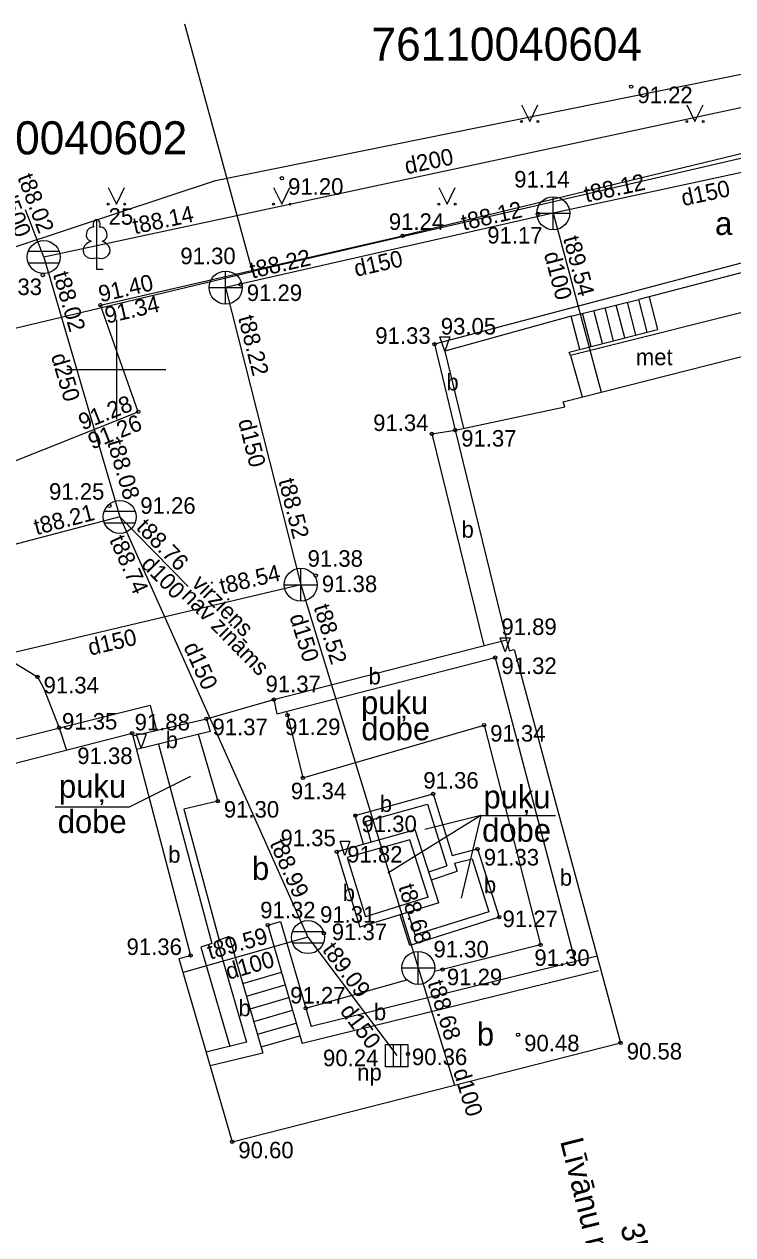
# Model space of a CAD drawing. Extents: x 634272 to 634544, y 247463 to 247653.
# Drawn here: x 634397.21 to 634418.64, y 247573.83 to 247610.44 of the extents above; entities that cross this region are included whole.
import ezdxf

# ---------------------------------------------------------------- set-up
doc = ezdxf.new("R2010")
doc.units = 0
for name, color, linetype in [('BUVE_BDET_####_####_#', 7, 'Continuous'), ('BUVE_BDET_####_TKST_#', 7, 'Continuous'), ('BUVE_EKAS_####_####_#', 7, 'Continuous'), ('BUVE_EKAS_BIZM_TKST_#', 7, 'Continuous'), ('BUVE_EKAS_RAKS_TKST_#', 7, 'Continuous'), ('CELI_CAPM_####_####_#', 7, 'Continuous'), ('CELI_CMAL_####_####_#', 7, 'Continuous'), ('CELI_CSEG_####_TKST_#', 7, 'Continuous'), ('GEOD_ELEM_####_####_#', 7, 'Continuous'), ('LKAN_ELEM_####_####_#', 7, 'Continuous'), ('LKAN_ELEM_PAST_TKST_#', 7, 'Continuous'), ('LKAN_VADP_PAST_####_#', 7, 'Continuous'), ('LKAN_VADP_PAST_TKST_#', 7, 'Continuous'), ('RAMI_UZMR_####_####_#', 7, 'Continuous'), ('RELJ_AATZ_####_TKST_#', 7, 'Continuous'), ('RELJ_ELEM_####_####_#', 7, 'Continuous'), ('ROBZ_KADS_####_TKST_#', 7, 'Continuous'), ('ROBZ_UZMR_####_####_#', 7, 'Continuous'), ('SKAN_ELEM_####_####_#', 7, 'Continuous'), ('SKAN_ELEM_PAST_TKST_#', 7, 'Continuous'), ('SKAN_VADP_PAST_####_#', 7, 'Continuous'), ('SKAN_VADP_PAST_TKST_#', 7, 'Continuous'), ('TERT_DIAM_####_TKST_#', 7, 'Continuous'), ('TERT_ELEM_####_####_#', 7, 'Continuous'), ('TERT_IZMT_####_TKST_#', 7, 'Continuous')]:
    doc.layers.add(name, color=color, linetype=linetype)

msp = doc.modelspace()

# ---------------------------------------------------------------- linework, layer by layer
at = {"layer": 'BUVE_BDET_####_####_#'}
for p, q in [((634415.714, 247601.044), (634415.459, 247602.033)), ((634416.053, 247601.131), (634415.798, 247602.116)), ((634416.372, 247601.214), (634416.12, 247602.189)), ((634414.02, 247600.605), (634413.759, 247601.615)), ((634414.359, 247600.693), (634414.099, 247601.699)), ((634414.698, 247600.781), (634414.439, 247601.782)), ((634415.037, 247600.868), (634414.779, 247601.866)), ((634415.376, 247600.956), (634415.119, 247601.949)), ((634407.47, 247585.638), (634407.227, 247586.507)), ((634407.711, 247585.705), (634407.535, 247586.333)), ((634409.449, 247584.803), (634409.992, 247584.985)), ((634409.435, 247584.035), (634407.533, 247583.447)), ((634409.751, 247583.871), (634407.368, 247583.134)), ((634404.965, 247583.308), (634405.888, 247580.131)), ((634404.577, 247583.195), (634405.617, 247579.617)), ((634403.046, 247582.719), (634403.937, 247579.652)), ((634403.407, 247582.855), (634404.432, 247579.326)), ((634414.542, 247582.253), (634405.888, 247580.131)), ((634403.821, 247581.429), (634404.991, 247581.769)), ((634403.933, 247581.045), (634405.103, 247581.385)), ((634404.045, 247580.661), (634405.215, 247581.001)), ((634404.156, 247580.277), (634405.326, 247580.617)), ((634404.268, 247579.893), (634405.438, 247580.233)), ((634403.937, 247579.652), (634402.714, 247579.352)), ((634404.379, 247579.509), (634405.549, 247579.849))]:
    msp.add_line(p, q, dxfattribs=at)
for points in [[(634424.638, 247604.603), (634424.692, 247604.432), (634415.797, 247602.116)], [(634421.031, 247603.777), (634409.625, 247600.763)], [(634421.911, 247601.206), (634420.687, 247600.92), (634422.13, 247595.421), (634421.912, 247595.323), (634420.138, 247602.03), (634413.732, 247600.418), (634413.69, 247600.52), (634416.369, 247601.213)], [(634413.759, 247601.615), (634415.797, 247602.116)], [(634413.759, 247601.615), (634409.931, 247600.553), (634410.496, 247598.221)], [(634409.625, 247600.763), (634410.243, 247598.168)], [(634413.732, 247600.418), (634414.092, 247599.169)], [(634409.541, 247598.049), (634410.243, 247598.168)], [(634409.541, 247598.049), (634411.109, 247591.647)], [(634404.764, 247590.016), (634411.797, 247591.824)], [(634404.848, 247589.588), (634411.46, 247591.288)], [(634411.46, 247591.288), (634413.872, 247582.088)], [(634404.764, 247590.016), (634404.848, 247589.588)], [(634401.024, 247589.834), (634389.457, 247586.939), (634390.714, 247581.751), (634391.293, 247581.906), (634391.704, 247580.059), (634391.004, 247579.905), (634391.958, 247576.222)], [(634401.024, 247589.834), (634401.217, 247589.086)], [(634400.501, 247588.918), (634402.721, 247589.438), (634402.832, 247589.051), (634400.608, 247588.51)], [(634401.274, 247588.672), (634402.884, 247582.635), (634402.556, 247582.531), (634403.431, 247579.528)], [(634407.227, 247586.507), (634409.579, 247587.163), (634410.155, 247585.305)], [(634407.535, 247586.333), (634409.412, 247586.857), (634409.992, 247584.985)], [(634409.751, 247583.871), (634409.036, 247586.076), (634406.663, 247585.412)], [(634409.435, 247584.035), (634408.872, 247585.771), (634406.978, 247585.24), (634407.533, 247583.447)], [(634410.155, 247585.305), (634410.926, 247585.497), (634411.579, 247583.435), (634408.875, 247582.582), (634408.582, 247583.51)], [(634406.663, 247585.412), (634407.368, 247583.134)], [(634410.229, 247585.065), (634410.759, 247585.198), (634411.265, 247583.598), (634409.038, 247582.896), (634408.821, 247583.584)], [(634409.526, 247584.565), (634410.303, 247584.825)], [(634410.229, 247585.065), (634410.303, 247584.825)], [(634404.577, 247583.195), (634404.965, 247583.308)], [(634403.407, 247582.855), (634403.046, 247582.719)], [(634414.582, 247581.815), (634405.617, 247579.617)], [(634404.432, 247579.326), (634402.836, 247578.935)]]:
    msp.add_lwpolyline(points, dxfattribs=at)
at = {"layer": 'BUVE_EKAS_####_####_#'}
for p, q in [((634411.88, 247591.488), (634412.036, 247591.53)), ((634401.891, 247582.186), (634402.242, 247582.278)), ((634401.891, 247582.186), (634403.502, 247576.642))]:
    msp.add_line(p, q, dxfattribs=at)
for points in [[(634410.243, 247598.168), (634413.566, 247598.866), (634413.511, 247599.021), (634419.188, 247600.462)], [(634410.243, 247598.168), (634411.88, 247591.488)], [(634412.036, 247591.53), (634415.25, 247579.63)], [(634390.22, 247586.366), (634400.481, 247588.996)], [(634400.481, 247588.996), (634402.242, 247582.278)], [(634403.502, 247576.642), (634415.25, 247579.63)]]:
    msp.add_lwpolyline(points, dxfattribs=at)
at = {"layer": 'CELI_CAPM_####_####_#'}
for points in [[(634426.327, 247605.556), (634425.634, 247608.152), (634408.658, 247604.045)], [(634380.207, 247592.753), (634383.979, 247594.191), (634384.583, 247592.406), (634392.046, 247595.29), (634400.663, 247598.72), (634399.516, 247601.947), (634408.658, 247604.045)], [(634395.598, 247591.923), (634397.613, 247590.703), (634397.795, 247590.369), (634398.265, 247589.164), (634398.489, 247588.485)]]:
    msp.add_lwpolyline(points, dxfattribs=at)
at = {"layer": 'CELI_CMAL_####_####_#'}
for points in [[(634402.721, 247589.438), (634404.764, 247590.016)], [(634405.143, 247589.664), (634405.64, 247587.645), (634411.12, 247589.246), (634412.83, 247582.595), (634409.619, 247581.788)], [(634402.477, 247588.965), (634403.064, 247586.946), (634402.042, 247586.7), (634403.104, 247582.741)], [(634405.728, 247580.682), (634408.785, 247581.538)]]:
    msp.add_lwpolyline(points, dxfattribs=at)
at = {"layer": 'GEOD_ELEM_####_####_#'}
for p, q in [((634400, 247601.5), (634400, 247600)), ((634398.5, 247600), (634400, 247600)), ((634400, 247600), (634400, 247598.5)), ((634400, 247600), (634401.5, 247600))]:
    msp.add_line(p, q, dxfattribs=at)
at = {"layer": 'LKAN_ELEM_####_####_#'}
for p, q in [((634397.335, 247603.575), (634398.271, 247603.575)), ((634397.335, 247603.225), (634398.271, 247603.225)), ((634399.633, 247595.715), (634400.569, 247595.715)), ((634399.633, 247595.365), (634400.569, 247595.365)), ((634405.325, 247583.006), (634406.261, 247583.006)), ((634405.325, 247582.656), (634406.261, 247582.656)), ((634408.367, 247579.588), (634408.367, 247578.913)), ((634408.592, 247579.588), (634408.592, 247578.913))]:
    msp.add_line(p, q, dxfattribs=at)
msp.add_lwpolyline([(634408.142, 247579.588), (634408.817, 247579.588), (634408.817, 247578.913), (634408.142, 247578.913)], close=True, dxfattribs=at)
for centre in [(634397.803, 247603.4), (634400.101, 247595.54), (634405.793, 247582.831)]:
    msp.add_circle(centre, 0.5, dxfattribs=at)
at = {"layer": 'LKAN_VADP_PAST_####_#'}
msp.add_line((634400.101, 247595.54), (634402.168, 247593.44), dxfattribs=at)
for points in [[(634421.946, 247608.566), (634397.803, 247603.4), (634400.101, 247595.54), (634405.793, 247582.831), (634408.48, 247579.25)], [(634397.803, 247603.4), (634397.255, 247604.833)], [(634400.101, 247595.54), (634381.824, 247590.733)], [(634405.793, 247582.831), (634402.015, 247581.761)]]:
    msp.add_lwpolyline(points, dxfattribs=at)
at = {"layer": 'RAMI_UZMR_####_####_#'}
msp.add_lwpolyline([(634357.63, 247590.775), (634379.264, 247596.642), (634392.424, 247602.216), (634402.994, 247605.715), (634421.735, 247609.504), (634423.082, 247609.702), (634425.783, 247608.304), (634427.755, 247600.855), (634433.048, 247602.581), (634454.806, 247608.92), (634459.819, 247587.798), (634462.766, 247575.147), (634466.614, 247558.36), (634469.076, 247546.545)], dxfattribs=at)
at = {"layer": 'RELJ_ELEM_####_####_#'}
for points in [[(634409.781, 247600.986), (634410.081, 247600.986), (634409.931, 247600.553)], [(634411.607, 247591.888), (634411.907, 247591.888), (634411.757, 247591.455)], [(634400.598, 247588.977), (634400.898, 247588.977), (634400.748, 247588.544)], [(634406.764, 247585.737), (634407.064, 247585.737), (634406.914, 247585.304)]]:
    msp.add_lwpolyline(points, close=True, dxfattribs=at)
for centre in [(634415.571, 247608.554), (634405.008, 247605.785), (634412.751, 247604.711), (634408.658, 247604.045), (634397.774, 247602.857), (634403.758, 247602.571), (634399.516, 247601.947), (634409.625, 247600.763), (634400.663, 247598.72), (634409.541, 247598.049), (634410.243, 247598.168), (634399.788, 247595.873), (634406.029, 247593.766), (634411.46, 247591.288), (634397.613, 247590.703), (634404.764, 247590.016), (634405.173, 247589.544), (634398.265, 247589.164), (634402.721, 247589.438), (634411.12, 247589.246), (634400.481, 247588.996), (634405.64, 247587.645), (634403.064, 247586.946), (634409.579, 247587.163), (634407.227, 247586.507), (634410.926, 247585.497), (634406.663, 247585.412), (634411.579, 247583.435), (634404.577, 247583.195), (634406.275, 247582.95), (634412.83, 247582.595), (634402.242, 247582.278), (634409.868, 247581.851), (634405.728, 247580.682), (634412.148, 247579.877), (634415.25, 247579.63), (634408.82, 247579.297), (634403.502, 247576.642)]:
    msp.add_circle(centre, 0.05, dxfattribs=at)
at = {"layer": 'ROBZ_UZMR_####_####_#'}
for points in [[(634404.114, 247602.967), (634402.07, 247610.443)], [(634424.328, 247607.646), (634404.114, 247602.967)], [(634394.943, 247600.778), (634404.114, 247602.967)]]:
    msp.add_lwpolyline(points, dxfattribs=at)
at = {"layer": 'SKAN_ELEM_####_####_#'}
for p, q in [((634413.214, 247604.226), (634413.214, 247605.226)), ((634412.714, 247604.726), (634413.714, 247604.726)), ((634403.305, 247601.976), (634403.305, 247602.976)), ((634402.805, 247602.476), (634403.805, 247602.476)), ((634405.576, 247592.989), (634405.576, 247593.989)), ((634405.076, 247593.489), (634406.076, 247593.489)), ((634409.131, 247581.399), (634409.131, 247582.399)), ((634408.631, 247581.899), (634409.631, 247581.899))]:
    msp.add_line(p, q, dxfattribs=at)
for centre in [(634413.214, 247604.726), (634403.305, 247602.476), (634405.576, 247593.489), (634409.131, 247581.899)]:
    msp.add_circle(centre, 0.5, dxfattribs=at)
at = {"layer": 'SKAN_VADP_PAST_####_#'}
for p, q in [((634413.214, 247604.726), (634414.66, 247599.313)), ((634405.576, 247593.489), (634385.552, 247588.751)), ((634409.131, 247581.899), (634410.222, 247578.351))]:
    msp.add_line(p, q, dxfattribs=at)
msp.add_lwpolyline([(634467.293, 247556.065), (634460.247, 247556.807), (634435.579, 247559.128), (634432.448, 247572.232), (634426.846, 247593.259), (634423.583, 247606.965), (634413.214, 247604.726), (634403.305, 247602.476), (634405.576, 247593.489), (634409.131, 247581.899)], dxfattribs=at)
at = {"layer": 'TERT_ELEM_####_####_#'}
for p, q in [((634412.25, 247608), (634412.5, 247607.5)), ((634412.5, 247607.5), (634412.75, 247608)), ((634417.25, 247608), (634417.5, 247607.5)), ((634417.5, 247607.5), (634417.75, 247608)), ((634399.75, 247605.5), (634400, 247605)), ((634400, 247605), (634400.25, 247605.5)), ((634404.75, 247605.5), (634405, 247605)), ((634405, 247605), (634405.25, 247605.5)), ((634409.75, 247605.5), (634410, 247605)), ((634410, 247605), (634410.25, 247605.5)), ((634399.402, 247603.381), (634399.402, 247603.034)), ((634399.402, 247603.034), (634399.602, 247603.034))]:
    msp.add_line(p, q, dxfattribs=at)
for points in [[(634399.402, 247604.534), (634399.402, 247603.381)], [(634399.492, 247604.302), (634399.491, 247604.303)]]:
    msp.add_lwpolyline(points, dxfattribs=at)
for centre, radius in [((634412.25, 247607.5), 0.028), ((634412.75, 247607.5), 0.0263), ((634417.25, 247607.5), 0.028), ((634417.75, 247607.5), 0.0263), ((634399.75, 247605), 0.028), ((634400.25, 247605), 0.0263), ((634404.75, 247605), 0.028), ((634405.25, 247605), 0.0263), ((634409.75, 247605), 0.028), ((634410.25, 247605), 0.0263)]:
    msp.add_circle(centre, radius, dxfattribs=at)
for centre, major_axis, ratio, start_param, end_param in [((634399.402, 247604.384), (0, -0.15), 0.707107, 3.14537, 5.287485), ((634399.402, 247604.384), (0, -0.15), 0.707107, 0.995701, 3.137816), ((634399.274, 247604.089), (-0.039, -0.212), 0.861323, 3.141593, 6.283185), ((634399.53, 247604.089), (0.039, -0.212), 0.861323, 0, 3.141593), ((634399.312, 247603.627), (0.307, 0.095), 0.814445, 1.570796, 4.752015), ((634399.492, 247603.627), (-0.307, 0.095), 0.814445, 1.531171, 4.712389)]:
    msp.add_ellipse(centre, major_axis=major_axis, ratio=ratio, start_param=start_param, end_param=end_param, dxfattribs=at)
at = {"layer": 'TERT_IZMT_####_TKST_#'}
for p, q in [((634400.4, 247586.772), (634402.25, 247587.704)), ((634398.147, 247586.772), (634400.4, 247586.772)), ((634411.023, 247586.509), (634408.207, 247584.769)), ((634411.023, 247586.509), (634409.333, 247586.091)), ((634411.023, 247586.509), (634410.431, 247584.011)), ((634411.023, 247586.509), (634413.277, 247586.509))]:
    msp.add_line(p, q, dxfattribs=at)

# ---------------------------------------------------------------- texts
at = {"layer": 'BUVE_BDET_####_TKST_#'}
for s, p in [('met', (634415.71, 247600.129)), ('b', (634409.981, 247599.367)), ('b', (634410.44, 247594.912)), ('b', (634407.628, 247590.475)), ('b', (634401.491, 247588.546)), ('b', (634407.968, 247586.617)), ('b', (634401.567, 247585.082)), ('b', (634413.411, 247584.386)), ('b', (634406.845, 247583.919)), ('b', (634411.115, 247584.158)), ('b', (634403.691, 247580.438)), ('b', (634407.788, 247580.318))]:
    msp.add_text(s, height=0.5, dxfattribs=at).set_placement(p)
at = {"layer": 'BUVE_EKAS_BIZM_TKST_#'}
msp.add_text('Līvānu novada dome', height=0.7, rotation=284.1272, dxfattribs=at).set_placement((634413.417, 247576.666))
at = {"layer": 'BUVE_EKAS_RAKS_TKST_#'}
msp.add_text('3MDz', height=0.7, rotation=284.4886, dxfattribs=at).set_placement((634415.234, 247574.079))
at = {"layer": 'CELI_CSEG_####_TKST_#'}
for s, p in [('a', (634418.108, 247604.069)), ('b', (634404.102, 247584.562)), ('b', (634410.903, 247579.551))]:
    msp.add_text(s, height=0.7, dxfattribs=at).set_placement(p)
at = {"layer": 'LKAN_ELEM_PAST_TKST_#'}
for s, p in [(' 91.26', (634400.538, 247595.636)), (' 91.31', (634405.976, 247583.267)), (' 90.24', (634406.064, 247578.928)), ('np', (634407.284, 247578.494))]:
    msp.add_text(s, height=0.5, dxfattribs=at).set_placement(p)
at = {"layer": 'LKAN_VADP_PAST_TKST_#'}
for s, rotation, p in [('d200', 12.0777, (634408.775, 247605.901)), ('t88.02', 290.9181, (634397, 247605.811)), ('d500', 290.9181, (634396.44, 247605.344)), ('t88.14', 12.0777, (634400.554, 247604.088)), ('t88.02', 286.2971, (634398.075, 247602.882)), ('d250', 286.2971, (634398.016, 247600.413)), ('t88.08', 286.2971, (634399.719, 247597.801)), ('t88.21', 14.7355, (634397.581, 247594.986)), ('t88.76', 314.5363, (634400.569, 247595.192)), ('t88.74', 294.1263, (634399.776, 247594.852)), ('d100', 314.5363, (634400.719, 247594.077)), ('virziens', 314.5363, (634402.249, 247593.495)), ('nav zināms', 314.5363, (634401.943, 247593.11)), ('d150', 294.1263, (634402.021, 247591.62)), ('t88.99', 294.1263, (634404.627, 247585.663)), ('t89.59', 15.817, (634402.83, 247582.148)), ('t89.09', 306.8827, (634406.206, 247582.439)), ('d100', 15.817, (634403.388, 247581.539)), ('d150', 306.8827, (634406.742, 247580.588))]:
    msp.add_text(s, height=0.5, rotation=rotation, dxfattribs=at).set_placement(p)
at = {"layer": 'RELJ_AATZ_####_TKST_#'}
for s, p in [(' 91.22', (634415.571, 247608.054)), (' 91.20', (634405.008, 247605.285)), (' 91.24', (634408.055, 247604.222)), (' 91.17', (634411.031, 247603.809)), (' 91.33', (634395.892, 247602.251)), (' 91.29', (634403.758, 247602.071)), (' 91.33', (634407.645, 247600.775)), (' 93.05', (634409.627, 247601.057)), (' 91.34', (634407.58, 247598.139)), (' 91.37', (634410.243, 247597.668)), (' 91.25', (634397.778, 247596.061)), (' 91.38', (634406.029, 247593.266)), (' 91.89', (634411.459, 247591.97)), (' 91.32', (634411.46, 247590.788)), (' 91.34', (634397.613, 247590.203)), (' 91.37', (634404.326, 247590.239)), (' 91.35', (634398.17, 247589.109)), (' 91.88', (634400.366, 247589.083)), (' 91.37', (634402.721, 247588.938)), (' 91.29', (634404.917, 247588.944)), (' 91.34', (634411.12, 247588.746)), (' 91.38', (634398.631, 247588.066)), (' 91.36', (634409.098, 247587.323)), (' 91.34', (634405.091, 247587.002)), (' 91.30', (634403.064, 247586.446)), (' 91.30', (634407.227, 247586.007)), (' 91.35', (634404.777, 247585.582)), (' 91.82', (634406.795, 247585.086)), (' 91.33', (634410.926, 247584.997)), (' 91.32', (634404.165, 247583.401)), (' 91.27', (634411.494, 247583.134)), (' 91.37', (634406.329, 247582.74)), (' 91.36', (634400.123, 247582.291)), (' 91.30', (634412.457, 247581.96)), (' 91.29', (634409.811, 247581.376)), (' 91.27', (634405.071, 247580.823)), (' 90.48', (634412.148, 247579.377)), (' 90.58', (634415.25, 247579.13)), (' 90.36', (634408.753, 247578.961)), (' 90.60', (634403.502, 247576.142))]:
    msp.add_text(s, height=0.5, dxfattribs=at).set_placement(p)
for s, rotation, p in [(' 91.40', 12.925, (634399.342, 247601.988)), (' 91.34', 12.925, (634399.531, 247601.342)), (' 91.28', 21.705, (634398.804, 247598.085)), (' 91.26', 21.705, (634399.093, 247597.506))]:
    msp.add_text(s, height=0.5, rotation=rotation, dxfattribs=at).set_placement(p)
at = {"layer": 'ROBZ_KADS_####_TKST_#'}
for s, p in [('76110040604', (634407.718, 247609.341)), ('76110040602', (634393.963, 247606.507))]:
    msp.add_text(s, height=1, dxfattribs=at).set_placement(p)
at = {"layer": 'SKAN_ELEM_PAST_TKST_#'}
for s, p in [(' 91.14', (634411.846, 247605.503)), (' 91.30', (634401.749, 247603.185)), (' 91.38', (634405.598, 247594.034)), (' 91.30', (634409.404, 247582.218))]:
    msp.add_text(s, height=0.5, dxfattribs=at).set_placement(p)
at = {"layer": 'SKAN_VADP_PAST_TKST_#'}
for s, rotation, p in [('t88.12', 12.1849, (634414.211, 247605.051)), ('d150', 12.1849, (634417.143, 247604.937)), ('t88.12', 12.793, (634410.499, 247604.201)), ('t89.54', 284.9514, (634413.509, 247603.968)), ('t88.22', 12.793, (634404.103, 247602.749)), ('d150', 12.793, (634407.249, 247602.801)), ('d100', 284.9514, (634412.927, 247603.496)), ('t88.22', 284.1817, (634403.679, 247601.57)), ('d150', 284.1817, (634403.679, 247598.444)), ('t88.52', 284.1817, (634404.899, 247596.639)), ('t88.54', 13.3123, (634403.188, 247593.196)), ('t88.52', 287.0523, (634405.962, 247592.816)), ('d150', 287.0523, (634405.23, 247592.532)), ('d150', 13.3123, (634399.206, 247591.342)), ('t88.68', 287.0523, (634408.523, 247584.355)), ('t88.68', 287.0907, (634409.407, 247581.444)), ('d100', 287.0907, (634410.18, 247578.782))]:
    msp.add_text(s, height=0.5, rotation=rotation, dxfattribs=at).set_placement(p)
at = {"layer": 'TERT_DIAM_####_TKST_#'}
msp.add_text('25', height=0.5, dxfattribs=at).set_placement((634399.764, 247604.379))
at = {"layer": 'TERT_IZMT_####_TKST_#'}
for s, p in [('puķu', (634407.4, 247589.575)), ('dobe', (634407.406, 247588.786)), ('puķu', (634398.264, 247587.048)), ('puķu', (634411.103, 247586.725)), ('dobe', (634398.227, 247585.979)), ('dobe', (634411.062, 247585.714))]:
    msp.add_text(s, height=0.7, dxfattribs=at).set_placement(p)

doc.saveas('drawing.dxf')
